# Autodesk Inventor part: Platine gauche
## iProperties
Author: Flavien MARTY
Shininess: 20.0
PropertySet Name: _Private Model Information
Created: 2001-10
Part Number: Platine gauche
Material: Par défaut
Document SubType Name: Modélisation
Designer: Flavien MARTY
Control State: 0
Master: False
Checked Out: False
PropertySet Name: Design Tracking Control
Density: 0.0
Volumn: 0.0
Area: 0.0
PropertySet Name: Model Information
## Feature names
1. Base1
